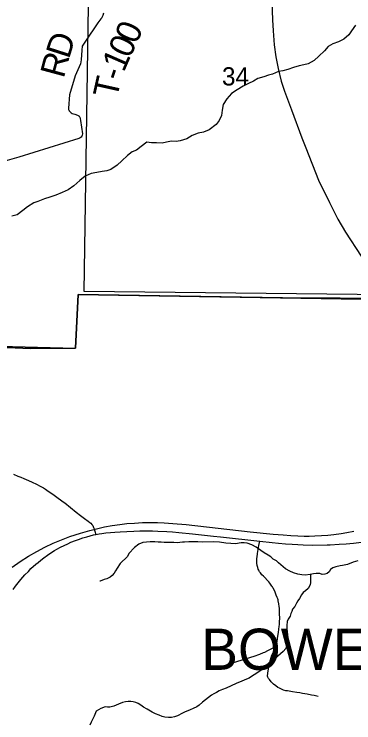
# Model space of a CAD drawing. Extents: x -1.2 to 34, y -8.5 to 22.
# Drawn here: x 5.304 to 6.085, y 16.749 to 18.378 of the extents above; entities that cross this region are included whole.
import ezdxf

# ---------------------------------------------------------------- set-up
doc = ezdxf.new("R2010")
doc.units = 0
for name, color, linetype in [('DV_X_County_Line', 7, 'Continuous'), ('GM_X_Corporation_Text', 7, 'Continuous'), ('GM_X_Minor_River', 7, 'Continuous'), ('GM_X_Rail_Line', 7, 'Continuous'), ('GM_X_Section', 7, 'Continuous'), ('GM_X_Section_Text', 7, 'Continuous'), ('GM_X_State_Route', 7, 'Continuous'), ('GM_X_Township_Road', 7, 'Continuous'), ('GM_X_Township_Road_Text', 7, 'Continuous'), ('GM_X_Unincorporated_Text', 7, 'Continuous'), ('SH_Cut_Line', 7, 'Continuous')]:
    doc.layers.add(name, color=color, linetype=linetype)

msp = doc.modelspace()

# ---------------------------------------------------------------- linework, layer by layer
at = {"layer": 'DV_X_County_Line'}
msp.add_lwpolyline([(2.4258, 17.6899), (5.4446, 17.6102), (5.4511, 17.7337), (6.5684, 17.7149)], dxfattribs=at)
at = {"layer": 'GM_X_Minor_River'}
for points in [[(6.0889, 18.3528), (6.0795, 18.3402), (6.0735, 18.3306), (6.0618, 18.3207), (6.0501, 18.3149), (6.0365, 18.3098), (6.0263, 18.304), (6.0176, 18.2937), (6.0048, 18.2818), (5.9939, 18.2719), (5.9799, 18.2642), (5.97, 18.2618), (5.9594, 18.2598), (5.9462, 18.2555), (5.9337, 18.2509), (5.9215, 18.2477), (5.9121, 18.2461), (5.8981, 18.2403), (5.8886, 18.238), (5.8784, 18.2345), (5.864, 18.2302), (5.8541, 18.224), (5.8432, 18.219), (5.8307, 18.2124), (5.8171, 18.2043), (5.8035, 18.1955), (5.7933, 18.1836), (5.7843, 18.1703), (5.7822, 18.1573), (5.7811, 18.1456), (5.7755, 18.1341), (5.7684, 18.1242), (5.7525, 18.1123), (5.7397, 18.1069), (5.7268, 18.1049), (5.7131, 18.0994), (5.7007, 18.0913), (5.6859, 18.0867), (5.6764, 18.0858), (5.6654, 18.0865), (5.654, 18.0841), (5.6442, 18.0818), (5.6312, 18.082), (5.6195, 18.0827), (5.6092, 18.0837), (5.596, 18.0737), (5.5854, 18.0657), (5.5756, 18.0614), (5.5646, 18.053), (5.5518, 18.0411), (5.5405, 18.0311), (5.5265, 18.0208), (5.5167, 18.0176), (5.5064, 18.0164), (5.4939, 18.0144), (5.4807, 18.0116), (5.4674, 18.0054), (5.455, 17.9958), (5.4414, 17.9832), (5.4278, 17.9744), (5.4142, 17.9685), (5.3998, 17.9623), (5.3858, 17.9577), (5.3733, 17.9538), (5.3585, 17.9476), (5.3487, 17.9441), (5.3347, 17.9352), (5.3234, 17.9268), (5.3109, 17.9168), (5.2984, 17.9136)], [(5.6713, 17.1629), (5.6619, 17.1631), (5.6539, 17.1634), (5.649, 17.1633), (5.6422, 17.1636), (5.6353, 17.1642), (5.6274, 17.1645), (5.6217, 17.1648), (5.6164, 17.1647), (5.6081, 17.1642), (5.6001, 17.1633), (5.5903, 17.1597), (5.5806, 17.152), (5.5672, 17.1381), (5.5646, 17.1308), (5.5474, 17.1149), (5.5408, 17.1045), (5.5367, 17.098), (5.5341, 17.093), (5.5293, 17.0876), (5.5244, 17.0833), (5.5169, 17.0794), (5.5109, 17.0782), (5.5014, 17.0746), (5.5005, 17.0742)], [(6.0945, 17.121), (6.0839, 17.1178), (6.0704, 17.1126), (6.059, 17.1101), (6.0534, 17.1093), (6.0439, 17.1076), (6.0372, 17.1049), (6.0312, 17.101), (6.0286, 17.0956), (6.0237, 17.0921), (6.0188, 17.0901), (6.012, 17.0896), (6.0067, 17.0918), (5.9987, 17.0921), (5.9923, 17.0912), (5.9847, 17.09), (5.973, 17.0879), (5.9658, 17.0885), (5.956, 17.0907), (5.9465, 17.0936), (5.9381, 17.0976), (5.9281, 17.1028), (5.9228, 17.1073), (5.9117, 17.1163), (5.9071, 17.1212), (5.8994, 17.1252), (5.8941, 17.1301), (5.8883, 17.1342), (5.8791, 17.1398), (5.8711, 17.145), (5.8608, 17.1524), (5.8509, 17.1576), (5.8395, 17.1613), (5.833, 17.1623), (5.8258, 17.1622), (5.813, 17.1605), (5.8024, 17.1611), (5.791, 17.162), (5.7758, 17.1637), (5.7618, 17.1646), (5.7376, 17.1643), (5.7262, 17.1645), (5.7137, 17.1647), (5.7058, 17.1646), (5.6959, 17.164), (5.691, 17.1636), (5.6785, 17.1626), (5.6713, 17.1629)], [(5.9855, 17.0901), (5.9858, 17.071), (5.9847, 17.0656), (5.9803, 17.0572), (5.9739, 17.0521), (5.9687, 17.0482), (5.9646, 17.0428), (5.9602, 17.0344), (5.9565, 17.0294), (5.9535, 17.0236), (5.9495, 17.0163), (5.9442, 17.0102), (5.9428, 17.0048), (5.9406, 16.9998), (5.9384, 16.9941), (5.934, 16.9872), (5.9318, 16.9814), (5.9312, 16.9723), (5.9313, 16.965), (5.9317, 16.9582), (5.9326, 16.9502), (5.9331, 16.9449), (5.9339, 16.9392), (5.934, 16.9335), (5.9314, 16.9254), (5.9285, 16.9197), (5.9229, 16.9124), (5.9102, 16.9015), (5.9009, 16.8938), (5.896, 16.8883), (5.89, 16.8833), (5.8867, 16.8783), (5.8784, 16.874), (5.872, 16.8697), (5.8597, 16.8611), (5.8522, 16.8565), (5.8447, 16.8514), (5.8379, 16.8486), (5.8277, 16.8443), (5.8146, 16.8391), (5.8029, 16.8336), (5.7916, 16.8285), (5.783, 16.8249), (5.7754, 16.8218), (5.769, 16.8183), (5.7634, 16.8155), (5.7574, 16.8124), (5.7506, 16.8069), (5.7372, 16.7957), (5.7293, 16.7895), (5.7241, 16.7856), (5.7158, 16.7813), (5.709, 16.7785), (5.703, 16.7758), (5.6974, 16.7738), (5.691, 16.771), (5.6797, 16.7647), (5.6725, 16.762), (5.6657, 16.7607), (5.6589, 16.761), (5.6502, 16.7616), (5.6441, 16.7634), (5.6376, 16.766), (5.6293, 16.7689), (5.6213, 16.7734), (5.6094, 16.78), (5.6014, 16.7849), (5.5949, 16.7893), (5.5888, 16.7927), (5.5838, 16.7956), (5.5774, 16.7967), (5.5724, 16.7974), (5.566, 16.7973), (5.5596, 16.7968), (5.5528, 16.7955), (5.5441, 16.7912), (5.5328, 16.7872), (5.5242, 16.7848), (5.5185, 16.7847), (5.5128, 16.785), (5.503, 16.7818), (5.4925, 16.7756), (5.4877, 16.7641), (5.4837, 16.756), (5.4811, 16.7503), (5.4778, 16.743)]]:
    msp.add_lwpolyline(points, dxfattribs=at)
at = {"layer": 'GM_X_Rail_Line'}
msp.add_lwpolyline([(5.2989, 17.1066), (5.3179, 17.1196), (5.3367, 17.1316), (5.3557, 17.1424), (5.3744, 17.1522), (5.3936, 17.1613), (5.4127, 17.1694), (5.4321, 17.1768), (5.456, 17.1849), (5.4775, 17.1909), (5.4932, 17.195), (5.5117, 17.199), (5.5295, 17.2021), (5.5471, 17.2047), (5.5633, 17.2066), (5.5803, 17.208), (5.5991, 17.209), (5.6183, 17.2092), (5.6334, 17.2092), (5.6487, 17.2083), (5.6689, 17.2072), (5.6992, 17.2044), (5.8469, 17.1878), (5.8993, 17.1827), (5.9224, 17.1805), (5.9403, 17.1792), (5.9566, 17.1784), (5.971, 17.1778), (5.9827, 17.1778), (5.9958, 17.1782), (6.0105, 17.179), (6.0251, 17.1801), (6.0395, 17.1817), (6.0558, 17.1836), (6.0694, 17.1859), (6.0855, 17.1892)], dxfattribs=at)
at = {"layer": 'GM_X_Section'}
msp.add_lwpolyline([(5.4804, 18.7665), (6.3194, 18.751), (6.3024, 17.731), (5.4646, 17.7402), (5.479, 18.6512)], close=True, dxfattribs=at)
at = {"layer": 'GM_X_State_Route'}
for points in [[(5.8959, 18.4268), (5.8984, 18.3655), (5.8993, 18.3396), (5.9019, 18.3076), (5.9059, 18.2804), (5.9111, 18.2534), (5.918, 18.224), (5.9256, 18.201), (5.9416, 18.1582), (5.9655, 18.094), (5.9747, 18.0711), (6.0042, 17.9964), (6.0289, 17.9455), (6.0487, 17.907), (6.066, 17.8772), (6.1018, 17.8215)], [(5.3013, 17.055), (5.307, 17.063), (5.3131, 17.0707), (5.3193, 17.0781), (5.3286, 17.0888), (5.3364, 17.0968), (5.3425, 17.1031), (5.3535, 17.1132), (5.3588, 17.1176), (5.3652, 17.1227), (5.3721, 17.1278), (5.3802, 17.1339), (5.3879, 17.1393), (5.3969, 17.1447), (5.4021, 17.1478), (5.4102, 17.1523), (5.4185, 17.1565), (5.427, 17.1605), (5.4342, 17.1637), (5.4445, 17.1678), (5.4515, 17.1704), (5.4616, 17.1738), (5.4707, 17.1766), (5.4784, 17.1786), (5.4865, 17.1805), (5.4918, 17.1816), (5.4992, 17.1831), (5.5052, 17.184), (5.5146, 17.1852), (5.5256, 17.1863), (5.5357, 17.1872), (5.5479, 17.188), (5.5629, 17.1888), (5.5788, 17.1893), (5.5929, 17.1897), (5.6084, 17.1898), (5.622, 17.1897), (5.6343, 17.1894), (5.6549, 17.1885), (5.6677, 17.1876), (5.6826, 17.1864), (5.7142, 17.1832), (5.7627, 17.178), (5.7781, 17.1762), (5.8687, 17.1665), (5.8976, 17.1633), (5.9119, 17.162), (5.9283, 17.1604), (5.9431, 17.1592), (5.9564, 17.1584), (5.9687, 17.1578), (5.9903, 17.1574), (6.024, 17.1576), (6.0306, 17.1579), (6.0513, 17.159), (6.0673, 17.1602), (6.0843, 17.1618), (6.1029, 17.1639)]]:
    msp.add_lwpolyline(points, dxfattribs=at)
at = {"layer": 'GM_X_Township_Road'}
for points in [[(5.5096, 18.3808), (5.5077, 18.3755), (5.5062, 18.3719), (5.5051, 18.3697), (5.5034, 18.3676), (5.4962, 18.3581), (5.468, 18.3161), (5.4606, 18.3046), (5.4596, 18.2951), (5.4581, 18.273), (5.4563, 18.2642), (5.4442, 18.2362), (5.4313, 18.193), (5.4287, 18.1618), (5.4289, 18.1592), (5.4293, 18.1582), (5.4302, 18.1562), (5.4323, 18.1535), (5.4333, 18.1526), (5.4351, 18.1513), (5.437, 18.1502), (5.4437, 18.1481), (5.4456, 18.1476)], [(5.4456, 18.1476), (5.4475, 18.147), (5.4493, 18.1463), (5.4507, 18.1455), (5.4522, 18.1446), (5.4531, 18.1437), (5.4536, 18.1431), (5.4541, 18.1425), (5.4545, 18.1417), (5.4554, 18.1387), (5.4563, 18.1338), (5.461, 18.1027), (5.4606, 18.1003), (5.4596, 18.0977), (5.4581, 18.0957), (5.4556, 18.094), (5.4528, 18.0927), (5.3145, 18.0496), (5.2822, 18.0402)], [(5.3023, 17.3205), (5.3122, 17.3161), (5.3189, 17.3133), (5.326, 17.3104), (5.3365, 17.3059), (5.3453, 17.3019), (5.3554, 17.297), (5.3638, 17.2927), (5.371, 17.2888), (5.3756, 17.2861), (5.3792, 17.2836), (5.3842, 17.28), (5.3925, 17.274), (5.3985, 17.2699), (5.4164, 17.2571), (5.4201, 17.2543), (5.4465, 17.2329), (5.4565, 17.2251), (5.4659, 17.2181), (5.4738, 17.2123), (5.4781, 17.2092), (5.4803, 17.2074), (5.4828, 17.2044), (5.4844, 17.202), (5.4864, 17.1978), (5.4878, 17.1943), (5.4893, 17.1895), (5.4918, 17.1816)], [(5.8637, 17.1376), (5.867, 17.156), (5.8687, 17.1665)], [(5.8969, 17.0627), (5.8951, 17.0652), (5.8916, 17.07), (5.8896, 17.0724), (5.877, 17.0855), (5.8735, 17.0892), (5.8702, 17.0932), (5.8683, 17.0959), (5.8677, 17.097), (5.8666, 17.0994), (5.8654, 17.1021), (5.8641, 17.1056), (5.8629, 17.1107), (5.8621, 17.1157), (5.862, 17.1213), (5.8621, 17.126), (5.8626, 17.1307), (5.8635, 17.1366), (5.8637, 17.1376)], [(6.0028, 16.8092), (5.9942, 16.811), (5.9876, 16.8123), (5.9778, 16.8143), (5.9668, 16.8161), (5.9608, 16.8171), (5.9537, 16.8183), (5.9441, 16.8199), (5.9362, 16.8211), (5.9324, 16.8217), (5.9288, 16.8223), (5.9237, 16.8237), (5.9206, 16.8248), (5.9171, 16.8263), (5.9141, 16.8279), (5.9107, 16.8299), (5.9055, 16.8334), (5.9007, 16.8375), (5.8951, 16.843), (5.8911, 16.8478), (5.889, 16.8507), (5.8874, 16.8534), (5.8868, 16.856), (5.8873, 16.8629), (5.8888, 16.8724), (5.8905, 16.8816), (5.8918, 16.888), (5.8931, 16.8937), (5.895, 16.8989), (5.896, 16.9016), (5.8976, 16.9056), (5.9007, 16.912), (5.9052, 16.922), (5.9056, 16.9232), (5.9061, 16.9247), (5.9071, 16.9287), (5.9082, 16.9337), (5.9086, 16.9363), (5.9101, 16.9476), (5.9115, 16.9565), (5.9127, 16.9641), (5.9135, 16.9699), (5.914, 16.9749), (5.9144, 16.9815), (5.9146, 16.9886), (5.9145, 16.9997), (5.9141, 17.0075), (5.9138, 17.0123), (5.9134, 17.0164), (5.9126, 17.0222), (5.9114, 17.029), (5.9109, 17.031), (5.91, 17.0338), (5.909, 17.0366), (5.9068, 17.0422), (5.9039, 17.0488), (5.9, 17.0575), (5.899, 17.0592), (5.898, 17.0609), (5.8969, 17.0627)], [(5.7839, 16.8791), (5.806, 16.8864), (5.8183, 16.8901), (5.8338, 16.8947), (5.8485, 16.8994), (5.8559, 16.9019), (5.869, 16.9066), (5.8776, 16.91), (5.8802, 16.9113), (5.887, 16.9147), (5.892, 16.9173), (5.9014, 16.9221), (5.9061, 16.9247)]]:
    msp.add_lwpolyline(points, dxfattribs=at)
at = {"layer": 'GM_X_Unincorporated_Text'}
for p, q in [((5.4511, 17.7337), (5.4446, 17.6102)), ((5.9208, 17.7258), (5.4511, 17.7337)), ((6.1864, 17.7242), (5.9208, 17.7258)), ((5.3422, 17.6091), (4.6867, 17.6371)), ((5.4446, 17.6102), (5.3422, 17.6091))]:
    msp.add_line(p, q, dxfattribs=at)
msp.add_lwpolyline([(4.4093, 17.6489), (4.6867, 17.6371), (5.3422, 17.6091), (5.4446, 17.6102), (5.4511, 17.7337), (5.9208, 17.7258), (6.1864, 17.7242), (6.3301, 17.7233), (6.5687, 17.7221)], dxfattribs=at)
at = {"layer": 'SH_Cut_Line'}
for points in [[(6.5687, 17.7221), (6.3301, 17.7233), (6.1864, 17.7242), (5.9208, 17.7258), (5.4511, 17.7337), (5.4446, 17.6102), (5.3422, 17.6091), (4.6867, 17.6371), (4.4093, 17.6489)], [(4.4093, 17.6489), (4.6867, 17.6371), (5.3422, 17.6091), (5.4446, 17.6102), (5.4511, 17.7337), (5.9208, 17.7258), (6.1864, 17.7242), (6.3301, 17.7233), (6.5687, 17.7221)]]:
    msp.add_lwpolyline(points, dxfattribs=at)

# ---------------------------------------------------------------- texts
at = {"layer": 'GM_X_Corporation_Text'}
msp.add_text('BOWERSTON', height=0.0947, rotation=0, dxfattribs=at).set_placement((5.7341, 16.8703))
at = {"layer": 'GM_X_Section_Text'}
msp.add_text('34', height=0.04186, rotation=0, dxfattribs=at).set_placement((5.7818, 18.2143))
at = {"layer": 'GM_X_Township_Road_Text'}
for s, rotation, p in [('0', 65.7696, (5.5847, 18.3071)), ('D', 72.258, (5.4296, 18.2735)), ('0', 65.0631, (5.5696, 18.2747)), ('R', 74.9532, (5.4177, 18.2291)), ('1', 66.4396, (5.5558, 18.2429)), ('T', 77.4456, (5.5401, 18.182)), ('-', 71.7057, (5.549, 18.2221))]:
    msp.add_text(s, height=0.0568, rotation=rotation, dxfattribs=at).set_placement(p)

doc.saveas('drawing.dxf')
